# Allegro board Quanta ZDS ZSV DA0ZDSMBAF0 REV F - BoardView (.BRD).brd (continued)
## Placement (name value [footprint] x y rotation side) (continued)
PC169  2200p/50v_4  [C0402]  90.6 23.38 0 bottom
PC170  *0.1u/10v_2  [C0201]  194.69 23.28 0 bottom
PC171  10u/25v_6  [C0603]  160.96 23.08 0 bottom
PC172  1000p/50v_2  [C0201]  188.77 22.88 180 bottom
PC173  0.1u/10v_2  [C0201]  194.69 22.39 180 bottom
PC174  2200p/50v_4  [C0402]  171.67 22.29 0 bottom
PC175  470p/50v_4x  [C0402]  184.51 22.25 0 bottom
PC176  1000p/50v_2  [C0201]  189.33 22.04 180 bottom
PC177  2200p/50v_4  [C0402]  160.4 21.94 180 bottom
PC178  1u/25v_4  [C0402]  179.57 8.11 90 bottom
PC179  *0.1u/10v_2  [C0201]  194.69 21.5 0 bottom
PC180  0.047u/25v_4x  [C0402]  71.76 21.49 0 bottom
PC181  0.1u/10v_2  [C0201]  189.33 21.28 180 bottom
PC182  330p/25v_2  [C0201]  170.63 21.24 90 bottom
PC183  33p/50v_2  [C0201]  172.18 21.22 270 bottom
PC184  10u/25v_6  [C0603]  94.18 20.87 180 bottom
PC185  0.1u/25v_4  [C0402]  160.4 20.95 180 bottom
PC186  0.1u/10v_2  [C0201]  194.69 20.61 0 bottom
PC187  *100p/50v_2  [C0201]  61.19 20.58 0 bottom
PC188  470p/50v_4x  [C0402]  171.42 20.23 180 bottom
PC189  1u/25v_6x  [C0603]  71.17 20.17 180 bottom
PC190  2200p/50v_4  [C0402]  59.9 20.12 270 bottom
PC191  100p/50v_2  [C0201]  62.85 19.79 180 bottom
PC192  0.1u/50v_6x  [C0603]  94.15 19.47 180 bottom
PC193  10u/10v_4  [C0402]  192.76 19.12 90 bottom
PC194  4700p/25v_4x  [C0402]  180.06 19.02 0 bottom
PC195  1000p/50v_2  [C0201]  175.34 18.99 90 bottom
PC196  1000p/50v_2  [C0201]  176.16 18.99 90 bottom
PC197  0.01u/10v_2  [C0201]  177.01 19.16 90 bottom
PC198  1000p/50v_2  [C0201]  178.56 18.99 90 bottom
PC199  330p/25v_2  [C0201]  177.79 19.16 270 bottom
PC200  2200p/50v_4  [C0402]  173.68 18.76 90 bottom
PC201  470p/50v_4x  [C0402]  181.39 18.6 270 bottom
PC202  1000p/50v_2  [C0201]  174.54 18.59 270 bottom
PC203  0.1u/25v_4  [C0402]  86.48 18.4 180 bottom
PC204  100p/50v_2  [C0201]  63.22 18.38 270 bottom
PC205  0.1u/25v_4  [C0402]  68.39 18.29 180 bottom
PC206  0.1u/10v_2  [C0201]  185.27 18.13 0 bottom
PC207  *390p/50v_4  [C0402]  180.06 17.97 0 bottom
PC208  10u/25v_6  [C0603]  73.79 17.83 0 bottom
PC209  *1000p/25v_2  [C0201]  64.13 17.73 0 bottom
PC210  1000p/50v_2  [C0201]  176.73 17.7 0 bottom
PC211  *100p/50v_4  [C0402]  171.04 17.69 90 bottom
PC212  10u/6.3v_6  [C0603]  178.56 2.78 180 bottom
PC213  10u/25v_6  [C0603]  86.47 17.14 180 bottom
PC214  0.1u/25v_4  [C0402]  67.86 16.88 270 bottom
PC215  0.1u/25v_4  [C0402]  68.86 16.88 90 bottom
PC216  10u/25v_6  [C0603]  73.77 16.41 0 bottom
PC217  10u/25v_6  [C0603]  86.47 15.75 180 bottom
PC218  *0.01u/50v_4x  [C0402]  80.42 15.42 180 bottom
PC219  10u/25v_6  [C0603]  73.74 14.94 0 bottom
PC220  *100p/50v_2  [C0201]  69.74 14.34 270 bottom
PC221  10u/25v_6  [C0603]  86.44 14.25 180 bottom
PC222  0.1u/25v_4  [C0402]  73.48 13.66 180 bottom
PC223  1u/25v_4  [C0402]  182.24 6.71 90 bottom
PC224  10u/25v_6  [C0603]  77.4 13.43 90 bottom
PC225  10u/25v_6  [C0603]  75.95 13.42 90 bottom
PC226  2200p/50v_4  [C0402]  74.81 13.21 90 bottom
PC227  0.1u/25v_4  [C0402]  82.29 12.89 270 bottom
PC228  2.2u/10v_4  [C0402]  182.37 14.21 0 bottom
PC229  *100p/50v_2  [C0201]  69.72 12.28 90 bottom
PC230  0.1u/50v_6x  [C0603]  92.32 9.08 0 bottom
PC231  2200p/50v_4  [C0402]  45.44 11.38 0 bottom
PC232  0.1u/25v_4  [C0402]  180.84 7.09 0 bottom
PC233  2.2u/10v_4  [C0402]  192.78 33.38 270 bottom
PC234  0.1u/50v_6x  [C0603]  92.32 10.57 0 bottom
PC235  1u/25v_4  [C0402]  198.75 31.86 270 bottom
PC236  1u/25v_6x  [C0603]  210.69 21.44 270 bottom
PC237  0.1u/25v_4  [C0402]  198.75 29.95 270 bottom
PC238  *10u/10v_4  [C0402]  78.25 46.06 0 bottom
PC239  10u/10v_4  [C0402]  84.63 59.01 270 bottom
PC240  1u/25v_6x  [C0603]  207.89 13.44 90 bottom
PC241  2.2u/10v_4  [C0402]  195.45 11.67 90 bottom
PC242  0.1u/25v_4  [C0402]  201.03 10.27 270 bottom
PC243  1u/25v_4  [C0402]  201.03 12.17 270 bottom
PC244  *2.2u/10v_4  [C0402]  191.76 33.38 270 bottom
PC245  1000p/50v_2  [C0201]  189.48 9.89 0 bottom
PC248  0.1u/10v_2  [C0201]  184.78 10.4 270 bottom
PC249  0.1u/10v_2  [C0201]  184.02 8.62 180 bottom
PC250  0.1u/10v_2  [C0201]  189.48 9 0 bottom
PC251  *0.1u/10v_2  [C0201]  184.14 9.51 90 bottom
PC255  22u/6.3v_6  [C0603]  190.87 6.15 90 bottom
PC256  *22u/6.3v_6  [C0603]  188.72 6.46 0 bottom
PD1  pmeg45a10epd  [D-5_8X4_3-3P]  91.92 16.37 0 bottom
PD2  rb521s30  [D-SOD523-1_2X0_8-1N4148WT-7]  184.02 13.36 90 bottom
PD3  udzvte-175.6b  [DSM]  66.52 14.11 180 bottom
PD4  1n4148wt-7  [D-SOD523-1_2X0_8-1N4148WT-7]  185.41 6.59 0 bottom
PD5  tvs_600w  [D-DO-214AC]  91.99 12.69 180 bottom
PD6  udzvte-175.6b  [DSM]  66.52 12.21 180 bottom
PD7  1n4448ws-7-f  [DSM]  92.54 7.37 0 bottom
PD9  1n4148wt-7  [D-SOD523-1_2X0_8-1N4148WT-7]  201.42 30.97 270 bottom
PD10  rb521s30  [D-SOD523-1_2X0_8-1N4148WT-7]  187.32 12.68 180 bottom
PD11  1n4148wt-7  [D-SOD523-1_2X0_8-1N4148WT-7]  207.64 9.76 270 bottom
PD12  rb521s30  [D-SOD523-1_2X0_8-1N4148WT-7]  188.72 27.16 270 bottom
PD13  1n4148wt-7  [D-SOD523-1_2X0_8-1N4148WT-7]  210.05 3.41 90 bottom
PL1  1.0uh/4.2a_4x4x1.2  [CHOKE-PCMB041B-1R0MS]  74.82 57.19 0 top
PL2  1.5uh/7.2a_7*7*1.5  [L6_6X6_47-1_3]  52.81 53.08 180 top
PL3  0.47uh/5a_4*4*1.2  [L4_2X4_2]  153.13 50.43 180 top
PL4  *0_8/s  [S0805]  160.8 47.87 270 top
PL5  3.3uh_5x5x1.8  [CHOKE-PCMB053T-1R0MS]  82.14 44.72 90 top
PL6  0.15uh/16.7a/7*7*1.5  [CHOKE-MPL73-1R5]  183.56 44.38 0 top
PL7  0.15uh/16.7a/7*7*1.5  [CHOKE-MPL73-1R5]  173.37 44.29 180 top
PL8  1uh/3.35a_2.5x2x1.2  [L3_2X2_5-1_55]  53.25 38.89 180 top
PL9  1.0uh/4.2a_4x4x1.2  [CHOKE-PCMB041B-1R0MS]  58.19 37.9 270 top
PL10  0.47uh/3.7a_2520  [L3_2X2_5-1_55]  68.6 37.3 270 top
PL11  *0_8/s  [S0805]  175.23 33.04 0 bottom
PL12  *0_8/s  [S0805]  181 33.01 180 bottom
PL13  1uh/3.35a_2.5x2x1.2  [L3_2X2_5-1_55]  160.82 29.73 90 bottom
PL14  4.7uh/1.8a_4*4*1.2  [CHOKE-PCMB041B-1R0MS]  79.53 21.76 270 bottom
PL15  *0_8/s  [S0805]  83.87 13.63 90 bottom
PQ1  aon7934  [POWER-3X3-65-10P]  73.96 53.08 270 top
PQ2  aon7934  [POWER-3X3-65-10P]  158.01 49.98 0 top
PQ3  aon7934  [POWER-3X3-65-10P]  61.84 48.61 180 top
PQ4  aon7934  [POWER-3X3-65-10P]  77.26 41.49 0 top
PQ5  aon7934  [POWER-3X3-65-10P]  62.35 38.09 0 top
PQ6  aon6998  [POWER-5X6-1_27-7P]  183.71 37.89 0 top
PQ7  aon6998  [POWER-5X6-1_27-7P]  173.4 37.73 180 top
PQ8  pja3411  [SOT23_213-3_3-2]  50.67 29.06 0 bottom
PQ9  mmdt2907a-7-f  [SOT363-2_1-65-6P]  59.96 25.93 180 bottom
PQ10  aon7934  [POWER-3X3-65-10P]  75.29 21.75 180 bottom
PQ11  aon7410  [WDFN5-3_05X3_05-65]  90.72 20.74 180 bottom
PQ12  aon7410  [WDFN5-3_05X3_05-65]  77.44 16.78 0 bottom
PQ14  aon7401  [WDFN5-3_05X3_05-65]  207.89 26.52 270 bottom
PQ15  me2n7002dkw-g_115ma  [SC70-2_1-65-6P]  212.72 22.08 90 bottom
PQ16  2n7002k_300ma  [SOT23_213-3_3-2]  181.86 3.92 270 bottom
PQ17  aon7401  [WDFN5-3_05X3_05-65]  207.89 21.7 90 bottom
PQ19  2n7002k_300ma  [SOT23_213-3_3-2]  200.78 34.78 0 bottom
PQ20  aon7401  [WDFN5-3_05X3_05-65]  210.69 13.19 270 bottom
PQ21  aon7401  [WDFN5-3_05X3_05-65]  210.69 8.36 90 bottom
PQ22  me2n7002dkw-g_115ma  [SC70-2_1-65-6P]  214.24 8.11 270 bottom
PQ23  mmdt2907a-7-f  [SOT363-2_1-65-6P]  192.53 13.82 0 bottom
PQ24  pja3411  [SOT23_213-3_3-2]  192.14 10.65 180 bottom
PQ26  mmdt2907a-7-f  [SOT363-2_1-65-6P]  194.18 26.91 0 bottom
PQ27  pja3411  [SOT23_213-3_3-2]  189.99 30.97 270 bottom
PQ28  2n7002k_300ma  [SOT23_213-3_3-2]  204.21 10.78 0 bottom
PR1  *0_6/s  [S0603]  86.13 59.2 0 top
PR2  *0_2/s  [S0201]  45.95 58.38 180 top
PR3  *0_8/s  [S0805]  54.73 57.77 0 top
PR4  *0_2/s  [S0201]  45.95 57.54 0 top
PR5  *0_2/s  [S0201]  156.66 56.45 270 top
PR6  *0_6/s  [S0603]  70.25 56.02 0 top
PR7  *0_8/s  [S0805]  79.37 53.33 0 top
PR8  *0_6/s  [S0603]  94.08 52.13 180 top
PR9  *0_6/s  [S0603]  62.61 51.58 180 top
PR10  *0_2  [R0201]  66.54 51.42 270 top
PR11  *10k/f_2  [R0201]  67.33 51.42 270 top
PR12  *0_2/s  [S0201]  68.12 51.42 270 top
PR13  *0_2/s  [S0201]  69.67 51.42 270 top
PR14  *0_2/s  [S0201]  70.5 51.42 270 top
PR15  *0_2/s  [S0201]  65.78 51.42 270 top
PR16  *0_2/s  [S0201]  152.22 50.43 180 top
PR17  *0_2/s  [S0201]  154.12 50.43 0 top
PR18  *0_2/s  [S0201]  75.56 50.43 90 top
PR19  *0_2/s  [S0201]  76.3 50.43 270 top
PR20  ntc_100k_4  [R0402]  170.84 49.09 0 top
PR21  ntc_100k_4  [R0402]  189.24 40.19 0 top
PR22  10k/f_2  [R0201]  51.43 45.91 0 top
PR23  *0_6/s  [S0603]  94.74 48.09 0 top
PR24  150_4  [R0402]  155.57 45.17 270 top
PR25  *0_4/s  [S0402]  189.73 12.05 270 bottom
PR26  *10k/f_2  [R0201]  51.43 45.14 180 top
PR27  *0_6/s  [S0603]  57.02 45.24 180 top
PR28  ntc_100k_4  [R0402]  151.61 47.11 180 top
PR29  *0_4/s  [S0402]  78.79 46.8 270 top
PR30  10k/f_2  [R0201]  51.43 43.87 180 top
PR31  24k/f_4  [R0402]  162.81 43.92 90 top
PR32  10k/f_2  [R0201]  58.41 43.42 270 top
PR33  *0_2/s  [S0201]  57.65 43.42 90 top
PR34  *0_2/s  [S0201]  181.66 44.39 180 top
PR35  *0_2/s  [S0201]  185.44 44.39 0 top
PR36  *0_2/s  [S0201]  175.23 44.34 0 top
PR37  *0_2/s  [S0201]  171.52 44.29 180 top
PR38  *0_2/s  [S0201]  58.41 41.89 90 top
PR39  10k/f_2  [R0201]  51.43 42.27 0 top
PR40  *10k/f_2  [R0201]  51.43 41.51 0 top
PR41  *r010_4  [R0402]  76.3 43.8 0 top
PR42  16.5k/f_2  [R0201]  63.21 46.29 0 top
PR43  *0_2/s  [S0201]  60.73 43.7 0 top
PR44  *0_2/s  [S0201]  60.7 41.99 0 top
PR45  *0_2/s  [S0201]  60.7 42.86 0 top
PR46  *0_6  [R0603]  91.74 42.46 180 top
PR47  *0_2/s  [S0201]  51.43 40.75 0 top
PR48  *0_6/s  [S0603]  86.35 42.28 90 top
PR49  10.2k/f_2  [R0201]  73.4 39.13 90 top
PR50  *0_6/s  [S0603]  71.52 38.22 270 top
PR51  *0_6/s  [S0603]  51.25 35.97 90 top
PR52  *0_6/s  [S0603]  75.35 37.71 90 top
PR53  ntc_100k_4  [R0402]  188.46 36.06 90 top
PR54  *0_2/s  [S0201]  66.17 35.1 90 top
PR55  *0_6/s  [S0603]  71.93 34.52 180 top
PR56  ntc_100k_4  [R0402]  168.47 34.24 90 top
PR57  *0_2/s  [S0201]  164.26 33.84 0 top
PR58  *0_6/s  [S0603]  81.91 59.35 180 bottom
PR59  2.2_6  [R0603]  75.36 55.23 270 bottom
PR60  *0_2/s  [S0201]  78.68 54.65 90 bottom
PR61  *0_2/s  [S0201]  79.83 54.63 90 bottom
PR62  *0_2/s  [S0201]  86.3 53.81 90 top
PR63  *0_2/s  [S0201]  83.84 53.86 90 bottom
PR64  *0_2  [R0201]  84.6 53.86 90 bottom
PR65  *0_2/s  [S0201]  86.3 52.71 270 top
PR66  2.2_6  [R0603]  73.98 52.59 90 bottom
PR67  *0_2  [R0201]  72.42 52.06 0 bottom
PR68  *100k/f_2  [R0201]  71.43 52.06 180 bottom
PR69  2.2_6  [R0603]  158.72 50.93 180 bottom
PR70  *0_2/s  [S0201]  88.92 50.76 180 bottom
PR71  *0_2/s  [S0201]  72.11 50.71 270 bottom
PR72  10.2k/f_2  [R0201]  71.24 50.69 90 bottom
PR73  *0_2/s  [S0201]  85.72 50.66 0 bottom
PR74  *0_2  [R0201]  88.92 50.05 180 bottom
PR75  *0_2/s  [S0201]  85.72 49.88 0 bottom
PR76  *0_2/s  [S0201]  74.85 49.62 270 bottom
PR77  *0_2/s  [S0201]  71.96 49.6 270 bottom
PR78  100/f_2  [R0201]  116.63 49.56 90 bottom
PR79  100/f_2  [R0201]  117.49 49.56 90 bottom
PR80  100/f_2  [R0201]  118.33 49.56 90 bottom
PR81  100/f_2  [R0201]  119.14 49.56 90 bottom
PR82  1_6  [R0603]  158.72 49.43 0 bottom
PR83  *0_4/s  [S0402]  75.59 49.32 90 bottom
PR84  *10k/f_2  [R0201]  64.93 49.12 180 bottom
PR85  *0_2  [R0201]  65.73 48.99 90 bottom
PR86  *0_2/s  [S0201]  66.59 48.99 90 bottom
PR87  *0_2/s  [S0201]  67.89 49.04 90 bottom
PR88  100k/f_2  [R0201]  68.78 48.99 90 bottom
PR89  *0_2/s  [S0201]  69.95 48.99 270 bottom
PR90  *0_2/s  [S0201]  61.34 48.96 270 bottom
PR91  *0_2/s  [S0201]  70.7 48.77 90 bottom
PR92  10k/f_2  [R0201]  71.57 48.71 0 bottom
PR93  *0_2/s  [S0201]  72.97 48.35 90 bottom
PR94  *0_2/s  [S0201]  73.68 48.35 90 bottom
PR95  *0_2/s  [S0201]  74.49 48.17 0 bottom
PR96  *0_2/s  [S0201]  64.69 48.17 180 bottom
PR97  *0_2/s  [S0201]  69.63 47.86 0 bottom
PR98  *0_2/s  [S0201]  90.42 47.86 180 bottom
PR99  *100k/f_2  [R0201]  71.57 47.31 0 bottom
PR100  *2.2_6  [R0603]  59.69 47.74 180 bottom
PR101  *100k/f_2  [R0201]  65.73 47.72 270 bottom
PR102  *0_2/s  [S0201]  66.49 47.72 270 bottom
PR103  *0_2/s  [S0201]  68.32 47.56 180 bottom
PR104  *10k/f_2  [R0201]  74.49 47.36 180 bottom
PR105  249k/f_2  [R0201]  69.63 47.09 180 bottom
PR106  2.2_6  [R0603]  63.57 46.68 90 bottom
PR107  *62k/f_2  [R0201]  68.4 46.45 0 bottom
PR108  1m/f_2  [R0201]  69.62 46.39 0 bottom
PR109  *0_2/s  [S0201]  66.87 46.37 270 bottom
PR110  *0_2/s  [S0201]  65.73 46.32 90 bottom
PR111  *0_2  [R0201]  91.46 45.98 180 bottom
PR112  *0_2  [R0201]  85.41 45.12 270 bottom
PR113  *0_2/s  [S0201]  86.13 45.12 270 bottom
PR114  *0_2/s  [S0201]  90.49 45.74 90 bottom
PR115  1k/f_2  [R0201]  69.69 45.43 90 bottom
PR116  *0_2/s  [S0201]  68.4 45.41 180 bottom
PR117  *10k/f_2  [R0201]  66.87 45.13 90 bottom
PR118  100/f_2  [R0201]  126.49 45.04 180 bottom
PR119  *10k/f_2  [R0201]  74.49 45 180 bottom
PR120  100k/f_2  [R0201]  71.72 44.77 0 bottom
PR121  *10k/f_2  [R0201]  51.43 43.87 0 bottom
PR122  100/f_2  [R0201]  125.6 44.48 90 bottom
PR123  *0_2/s  [S0201]  68.4 44.39 180 bottom
PR124  *0_2  [R0201]  69.79 44.39 180 bottom
PR125  *0_2  [R0201]  75.91 44.36 90 bottom
PR126  *0_2/s  [S0201]  70.68 44.26 270 bottom
PR127  *0_2/s  [S0201]  74.59 44.16 180 bottom
PR128  *10k/f_2  [R0201]  66.87 43.91 270 bottom
PR129  *0_2  [R0201]  51.43 43.03 0 bottom
PR130  10.2k/f_2  [R0201]  68.4 43.4 180 bottom
PR131  100k/f_2  [R0201]  69.82 43.4 0 bottom
PR132  *0_2/s  [S0201]  70.86 43.3 90 bottom
PR133  *57.6k/f_2  [R0201]  73.73 43.14 180 bottom
PR134  *0_2/s  [S0201]  69.31 42.65 180 bottom
PR135  *0_2/s  [S0201]  51.43 42.27 180 bottom
PR136  *0_2/s  [S0201]  72.51 42.53 270 bottom
PR137  2.2_6  [R0603]  61.87 42.23 180 bottom
PR138  *0_2/s  [S0201]  73.73 42.13 180 bottom
PR139  2.2_6  [R0603]  80.61 42.1 90 bottom
PR140  100k/f_2  [R0201]  69.79 41.93 0 bottom
PR141  *2.2_6  [R0603]  52.6 40.19 90 bottom
PR142  *0_2  [R0201]  65.22 41.49 270 bottom
PR143  *0_2/s  [S0201]  66.13 41.49 270 bottom
PR144  2.2_6  [R0603]  76.42 41.47 0 bottom
PR145  *0_4/s  [S0402]  56.6 40.34 90 bottom
PR146  *0_2/s  [S0201]  67.89 41.21 180 bottom
PR147  *0_2/s  [S0201]  65.09 40.33 90 bottom
PR148  *10k/f_2  [R0201]  70.91 40.27 90 bottom
PR149  *0_2/s  [S0201]  72.61 40.27 90 bottom
PR150  100k/f_2  [R0201]  73.96 40.27 270 bottom
PR151  *0_2/s  [S0201]  66.49 40.22 90 bottom
PR152  *0_2  [R0201]  68.12 40.22 270 bottom
PR153  *0_2  [R0201]  68.85 40.22 270 bottom
PR154  *2.2_6  [R0603]  59.03 40.15 270 bottom
PR155  *0_2/s  [S0201]  67.3 39.87 270 bottom
PR156  100k/f_2  [R0201]  70.02 39.18 270 bottom
PR157  100k/f_2  [R0201]  66.52 39.16 270 bottom
PR158  100k/f_2  [R0201]  68.27 39.16 270 bottom
PR159  100k/f_2  [R0201]  69.21 39.16 270 bottom
PR160  100k/f_2  [R0201]  70.91 39.16 270 bottom
PR161  *0_2/s  [S0201]  71.77 39.16 270 bottom
PR162  *0_2  [R0201]  72.61 39.16 90 bottom
PR163  2.2_6  [R0603]  172.94 38.75 270 bottom
PR164  2.2_6  [R0603]  183.36 38.6 270 bottom
PR165  100/f_2  [R0201]  53.74 36.97 180 bottom
PR166  *0_2/s  [S0201]  52.42 36.97 180 bottom
PR167  100/f_2  [R0201]  53.72 35.97 0 bottom
PR168  *0_2/s  [S0201]  113.84 35.36 270 bottom
PR169  *0_2/s  [S0201]  114.89 35.35 270 bottom
PR170  *0_2/s  [S0201]  80.61 34.86 90 bottom
PR171  *0_6/s  [S0603]  62.15 34.38 90 bottom
PR172  *0_2/s  [S0201]  54.25 33.83 0 bottom
PR173  *0_2/s  [S0201]  69.97 33.75 180 bottom
PR174  *0_2/s  [S0201]  54.25 33.15 0 bottom
PR175  100/f_2  [R0201]  69.97 32.93 180 bottom
PR176  *0_6/s  [S0603]  159.35 32.77 0 bottom
PR177  *0_8/s  [S0805]  59.33 32.59 0 bottom
PR178  *0_6/s  [S0603]  76.12 31.59 270 bottom
PR179  *0_6/s  [S0603]  81.86 30.77 90 bottom
PR180  *2.2_6  [R0603]  163.63 30.28 0 bottom
PR181  1_6  [R0603]  175.23 30.27 270 bottom
PR182  2.2_6  [R0603]  172.31 30.24 270 bottom
PR183  1_6  [R0603]  181.1 30.22 270 bottom
PR184  243k/f_4  [R0402]  170.05 29.86 90 bottom
PR185  14k/f_4  [R0402]  176.4 29.86 90 bottom
PR186  4.32k/f_4  [R0402]  171.04 29.86 90 bottom
PR187  11k/f_4  [R0402]  178.94 29.86 90 bottom
PR188  11k/f_4  [R0402]  179.88 29.81 90 bottom
PR189  15.8k/f_4  [R0402]  184.37 29.73 180 bottom
PR190  *0_2/s  [S0201]  183.99 28.86 180 bottom
PR191  *0_2/s  [S0201]  184.86 28.62 270 bottom
PR192  *0_2/s  [S0201]  185.64 28.62 270 bottom
PR193  931/f_4  [R0402]  187.37 29.04 90 bottom
PR194  1k/f_2  [R0201]  169.74 27.96 180 bottom
PR195  *0_2  [R0201]  158.47 27.9 0 bottom
PR196  *0_4/s  [S0402]  163.99 27.86 180 bottom
PR197  2k/f_2  [R0201]  187.27 27.52 270 bottom
PR198  *0_2/s  [S0201]  71.83 27.46 180 bottom
PR199  *0_2  [R0201]  73.26 27.46 180 bottom
PR200  1k/f_2  [R0201]  184.57 27.24 90 bottom
PR201  15.8k/f_4  [R0402]  169.41 27 0 bottom
PR202  510k_2  [R0201]  57.52 26.87 180 bottom
PR203  *0_2/s  [S0201]  171.02 26.8 0 bottom
PR204  100k/f_2  [R0201]  68.56 26.74 0 bottom
PR205  10k/f_2  [R0201]  157.63 26.68 270 bottom
PR206  *10k/f_2  [R0201]  158.64 26.68 270 bottom
PR207  1k/f_2  [R0201]  185.85 26.64 0 bottom
PR208  *0_4  [R0402]  34.08 26.47 90 bottom
PR209  *0_2  [R0201]  71.85 26.37 180 bottom
PR210  *0_2/s  [S0201]  73.25 26.37 180 bottom
PR211  *0_4/s  [S0402]  55.92 26.23 180 bottom
PR212  10/f_4  [R0402]  65.48 26.59 270 bottom
PR213  10/f_4  [R0402]  170.66 26.02 0 bottom
PR214  1k/f_2  [R0201]  57.42 26.01 180 bottom
PR215  18.7k/f_4  [R0402]  68.85 25.82 180 bottom
PR216  *100k/f_2  [R0201]  64.52 25.74 90 bottom
PR217  220k_2  [R0201]  61.86 25.63 90 bottom
PR218  *2.2_6  [R0603]  79.37 25.54 180 bottom
PR219  *0_6/s  [S0603]  190.7 25.79 90 bottom
PR220  *1k/f_2  [R0201]  57.42 25.14 180 bottom
PR221  11k/f_4  [R0402]  184.43 25.14 180 bottom
PR222  *0_2/s  [S0201]  164.55 25.12 270 bottom
PR223  *0_4  [R0402]  55.92 24.92 180 bottom
PR224  *0_2/s  [S0201]  168.47 24.79 270 bottom
PR225  *0_2  [R0201]  63.83 24.74 180 bottom
PR226  1m/f_2  [R0201]  61.86 24.46 270 bottom
PR227  *10k/f_2  [R0201]  158.51 23.6 180 bottom
PR228  7.5k/f_2  [R0201]  186.56 24.32 90 bottom
PR229  220k_2  [R0201]  60.01 24.28 180 bottom
PR230  *0_2/s  [S0201]  196.18 24.17 180 bottom
PR231  *0_2/s  [S0201]  163.04 24.05 0 bottom
PR232  165k/f_4  [R0402]  169.71 24.04 180 bottom
PR233  10k/f_2  [R0201]  164.46 24.02 0 bottom
PR234  *0_2/s  [S0201]  62.79 23.96 0 bottom
PR235  *0_4/s  [S0402]  175.38 10.27 270 bottom
PR236  10k/f_2  [R0201]  158.51 22.92 0 bottom
PR237  14k/f_4  [R0402]  186.48 23.35 180 bottom
PR238  *0_2  [R0201]  196.18 23.28 180 bottom
PR239  *0_2/s  [S0201]  62.77 23.19 0 bottom
PR240  75k/f_2  [R0201]  170.28 23.1 90 bottom
PR241  15.8k/f_4  [R0402]  168.97 23.08 180 bottom
PR242  *0_4/s  [S0402]  71.76 22.53 0 bottom
PR243  10k/f_2  [R0201]  158.51 22.19 0 bottom
PR244  *0_2/s  [S0201]  62.75 22.43 0 bottom
PR245  *0_2  [R0201]  196.18 22.39 0 bottom
PR246  *0_6/s  [S0603]  163.69 22.32 180 bottom
PR247  21k/f_4  [R0402]  186.47 22.25 180 bottom
PR248  49.9/f_2  [R0201]  170.22 22.19 180 bottom
PR249  15.4k/f_4  [R0402]  60.75 21.61 0 bottom
PR250  *0_2/s  [S0201]  196.18 21.5 0 bottom
PR251  *10k/f_2  [R0201]  158.54 21.43 180 bottom
PR252  1k/f_2  [R0201]  169.82 21.24 90 bottom
PR253  3.3k/f_2  [R0201]  171.42 21.21 270 bottom
PR254  10/f_4  [R0402]  184.55 21.2 0 bottom
PR255  88.7k/f_4  [R0402]  168.96 20.87 270 bottom
PR256  *0_4/s  [S0402]  62.47 20.76 180 bottom
PR257  220/f_2  [R0201]  185.27 20.46 0 bottom
PR258  *0_2/s  [S0201]  182.22 20.38 90 bottom
PR259  *0_2/s  [S0201]  183.82 20.29 180 bottom
PR260  rc1206-r010  [F3_2X1_65-2_8]  85.81 20.26 180 bottom
PR261  *0_2/s  [S0201]  86.52 20.26 0 bottom
PR262  *0_2/s  [S0201]  85.07 20.23 180 bottom
PR263  *0_2  [R0201]  159.33 19.91 90 bottom
PR264  *0_2/s  [S0201]  158.3 19.91 90 bottom
PR265  75/f_2  [R0201]  187.24 19.82 90 bottom
PR266  300/f_4  [R0402]  61.47 19.76 180 bottom
PR267  *56.2/f_2  [R0201]  185.27 19.68 180 bottom
PR268  *75/f_2  [R0201]  186.33 19.6 0 bottom
PR269  49.9/f_2  [R0201]  183.82 19.55 0 bottom
PR270  39k/f_4  [R0402]  171.42 19.19 0 bottom
PR271  *0_6/s  [S0603]  190.9 19.17 90 bottom
PR272  100/f_2  [R0201]  185.27 18.91 180 bottom
PR273  24.3k/f_4  [R0402]  182.84 18.61 270 bottom
PR274  10k/f_2  [R0201]  64.14 18.44 0 bottom
PR275  1k/f_2  [R0201]  172.71 19.16 270 bottom
PR276  100k/f_2  [R0201]  65.43 18.33 270 bottom
PR277  4.02k/f_2  [R0201]  66.37 18.31 270 bottom
PR278  4.02k/f_2  [R0201]  67.13 18.31 270 bottom
PR279  300/f_4  [R0402]  62.31 18.09 270 bottom
PR280  10/f_8  [R0805]  70.84 17.86 270 bottom
PR281  1k/f_2  [R0201]  177.7 17.67 0 bottom
PR282  *44.2k/f_4  [R0402]  172.05 17.69 270 bottom
PR283  10k/f_4  [R0402]  178.71 17.51 270 bottom
PR284  536/f_4  [R0402]  175.66 17.46 90 bottom
PR285  *0_2/s  [S0201]  174.82 17.39 90 bottom
PR286  *0_2/s  [S0201]  173.34 17.37 90 bottom
PR287  *0_2/s  [S0201]  174.06 17.36 90 bottom
PR288  100k/f_2  [R0201]  65.43 17.29 270 bottom
PR289  rc1206-r010  [F3_2X1_65-2_8]  82.53 17.2 0 bottom
PR290  *0_2/s  [S0201]  83.21 17.2 0 bottom
PR291  *0_2/s  [S0201]  81.82 17.17 180 bottom
PR292  62k/f_2  [R0201]  64.14 17.05 0 bottom
PR293  14k/f_4  [R0402]  180.03 17.03 0 bottom
PR294  *0_2/s  [S0201]  182.14 17.01 90 bottom
PR295  7.5k/f_2  [R0201]  181.35 17.01 90 bottom
PR296  1k/f_2  [R0201]  177.67 16.98 180 bottom
PR297  *0_2  [R0201]  183.18 16.96 90 bottom
PR298  *0_2/s  [S0201]  183.97 16.96 90 bottom
PR299  *0_2/s  [S0201]  184.55 16.96 90 bottom
PR300  51.1k/f_4  [R0402]  185.53 16.59 270 bottom
PR301  *0_2/s  [S0201]  176.42 16.2 90 bottom
PR302  *0_2/s  [S0201]  177.16 16.2 90 bottom
PR303  10k/f_2  [R0201]  182.27 16.09 180 bottom
PR304  *0_2/s  [S0201]  67.84 15.5 0 bottom
PR305  12.4k/f_4  [R0402]  176.78 3.03 90 bottom
PR306  10k/f_4  [R0402]  175 3.03 90 bottom
PR307  14k/f_4  [R0402]  175.89 3.03 270 bottom
PR308  *0_2/s  [S0201]  80.34 14.53 0 bottom
PR309  330_4  [R0402]  71.09 13.58 0 bottom
PR310  470_6  [R0603]  210.59 25.89 90 bottom
PR311  *0_4/s  [S0402]  183.13 6.71 270 bottom
PR312  1m_4  [R0402]  78.86 12.89 90 bottom
PR313  100_4  [R0402]  80.26 12.89 270 bottom
PR314  330_4  [R0402]  71.09 12.64 0 bottom
PR315  18.7k/f_4  [R0402]  182.37 13.19 180 bottom
PR316  1m/f_2  [R0201]  184.4 5.32 0 bottom
PR317  10k/f_2  [R0201]  180.76 13.19 180 bottom
PR318  100k/f_2  [R0201]  209.92 24.11 180 bottom
PR319  10k/f_2  [R0201]  183.25 5.32 180 bottom
PR320  10k/f_2  [R0201]  180.97 6.33 0 bottom
PR321  100k/f_2  [R0201]  208.91 24.11 180 bottom
PR324  100k/f_2  [R0201]  213.48 19.41 180 bottom
PR325  27.4k/f_4  [R0402]  192.78 31.48 270 bottom
PR326  100k/f_2  [R0201]  214.5 19.41 270 bottom
PR327  *0_4/s  [S0402]  199.64 31.86 90 bottom
PR328  10k/f_2  [R0201]  214.75 18.14 180 bottom
PR330  *0_2/s  [S0201]  213.48 18.14 180 bottom
PR331  10k/f_2  [R0201]  200.27 30.08 270 bottom
PR332  10.2k/f_2  [R0201]  192.78 29.95 270 bottom
PR334  10k/f_2  [R0201]  199.64 30.08 90 bottom
PR335  *100k/f_2  [R0201]  212.59 18.14 270 bottom
PR337  1m/f_2  [R0201]  201.67 37.19 90 bottom
PR340  *0_2  [R0201]  65.09 47.23 90 bottom
PR341  *0_2  [R0201]  158.54 20.73 0 bottom
PR342  *0_2  [R0201]  158.51 24.43 0 bottom
PR491  *10k/f_2  [R0201]  62.81 3.21 90 bottom
PR492  *0_2/s  [S0201]  176.27 12.3 270 bottom
PR493  *0_2/s  [S0201]  175.51 12.22 270 bottom
PR494  *0_2  [R0201]  177.03 12.3 270 bottom
PR495  10k/f_2  [R0201]  180.08 14.45 270 bottom
PR496  *100k/f_2  [R0201]  213.35 14.97 180 bottom
PR497  470_6  [R0603]  212.34 5.19 180 bottom
PR498  *100k/f_2  [R0201]  217.42 13.44 180 bottom
PR499  10k/f_2  [R0201]  213.99 11.67 0 bottom
PR500  *100k/f_2  [R0201]  217.42 14.21 180 bottom
PR501  100k/f_2  [R0201]  214.12 10.78 0 bottom
PR502  *0_2/s  [S0201]  215.26 11.67 0 bottom
PR503  100k/f_2  [R0201]  212.97 10.78 180 bottom
PR504  100k/f_2  [R0201]  211.96 10.78 180 bottom
PR505  100k/f_2  [R0201]  215.26 10.78 0 bottom
PR506  220k_2  [R0201]  194.68 13.82 180 bottom
PR507  27.4k/f_4  [R0402]  194.56 11.67 270 bottom
PR508  10k/f_2  [R0201]  201.92 9.51 270 bottom
PR509  1k/f_2  [R0201]  194.68 14.59 0 bottom
PR510  1m/f_2  [R0201]  206.5 12.05 90 bottom
PR512  1m/f_2  [R0201]  190.49 14.84 180 bottom
PR513  1m/f_2  [R0201]  194.68 13.06 0 bottom
PR514  220k_2  [R0201]  190.49 14.08 0 bottom
PR515  *0_4/s  [S0402]  201.92 12.17 270 bottom
PR516  10.2k/f_2  [R0201]  194.56 10.27 270 bottom
PR517  10k/f_2  [R0201]  201.92 10.65 270 bottom
PR518  1m/f_2  [R0201]  194.68 28.56 0 bottom
PR519  220k_2  [R0201]  196.56 26.65 90 bottom
PR520  220k_2  [R0201]  192.53 28.43 270 bottom
PR521  1k/f_2  [R0201]  196.34 27.79 0 bottom
PR522  *0_4/s  [S0402]  190.11 28.05 90 bottom
PR523  1m/f_2  [R0201]  193.54 28.56 0 bottom
PR524  *0_6/s  [S0603]  188.72 7.73 180 bottom
PR525  *0_2/s  [S0201]  184.78 9.51 270 bottom
PR526  *0_6/s  [S0603]  40.25 55.23 270 top
PU1  aoz1331di  [SON14-3X2-4-15P-SMT]  82.67 56.64 0 top
PU2  ncp81253  [DFN8-2X2-5-9P-NCP5901]  157.06 54.27 180 top
PU3  aoz1331di  [SON14-3X2-4-15P-SMT]  91.61 49.42 270 top
PU4  tmp708aidbvr  [SOT23-5-2_8-95-5P-G708]  159.89 44.13 0 top
PU5  tps650832  [BGA168-TEXAS-TPS650830ZAJT]  69.52 45.23 180 top
PU6  aoz1331di  [SON14-3X2-4-15P-SMT]  88.82 44.67 180 top
PU7  nb681agd-z  [QFN13-2X3-5]  54.51 42.57 180 top
PU8  mc74vhc1g08dft2g  [SOT353-1-2_125-65-5P]  88.56 52.93 180 top
PU9  aoz1331di  [SON14-3X2-4-15P-SMT]  79.17 32.1 0 bottom
PU10  mc74vhc1g08dft2g  [SOT353-1-2_125-65-5P]  76 27.47 180 bottom
PU11  nb681agd-z  [QFN13-2X3-5]  161.36 25.83 180 bottom
PU12  ncp81206  [QFN52-6X6-4-53P-1H]  178.12 24.46 90 bottom
PU13  aoz1331di  [SON14-3X2-4-15P-SMT]  191.99 22.55 270 bottom
PU14  bq24780sruyr  [QFN28-4X4-4-38P]  66.43 22.08 180 bottom
PU15  g9661mre1u  [TDFN10-3X3-5-11P-APL5620QBI-TRG]  177.21 6.92 180 bottom
PU16  ap2204k-adjtrg1  [SOT23-5-2_8-95-5P-1_3H]  181.93 10.14 270 bottom
PU17  ap2204k-adjtrg1  [SOT23-5-2_8-95-5P-1_3H]  195.7 30.84 0 bottom
PU18  *mc74vhc1g08dft2g  [SOT353-1-2_125-65-5P]  213.99 16.62 180 bottom
PU19  mc74vhc1g08dft2g  [SOT353-1-2_125-65-5P]  177.03 14.33 180 bottom
PU20  *mc74vhc1g08dft2g  [SOT353-1-2_125-65-5P]  214.88 13.44 0 bottom
PU21  ap2204k-adjtrg1  [SOT23-5-2_8-95-5P-1_3H]  198.24 11.54 0 bottom
PU22  aoz1331di  [SON14-3X2-4-15P-SMT]  186.94 10.14 90 bottom
Q1  dmg301nu-7_220ma  [SOT23_213-3_3-2]  103.47 58.49 180 top
Q2  metr3904-g_200ma  [SOT23_213-3_3-2]  98.52 58.46 0 top
Q3  metr3904-g_200ma  [SOT23_213-3_3-2]  108.17 58.46 180 top
Q4  *2n7002k_300ma  [SOT23_213-3_3-2]  192.02 39.99 0 top
Q8  *pja138k_500ma  [SOT23_213-3_3-2]  186.81 32.75 180 bottom
Q10  *14@me2n7002dkw-g_115ma  [SC70-2_1-65-6P]  190.37 48.55 90 bottom
Q11  *14@me2n7002dkw-g_115ma  [SC70-2_1-65-6P]  194.33 48.5 90 bottom
Q12  2n7002k_300ma  [SOT23_213-3_3-2]  198.29 39.99 0 bottom
Q13  *2n7002k_300ma  [SOT23_213-3_3-2]  193.42 39.66 0 bottom
Q14  *2n7002k_300ma  [SOT23_213-3_3-2]  93.54 27.64 90 bottom
Q15  2n7002k_300ma  [SOT23_213-3_3-2]  90.85 25.94 180 bottom
Q16  *pj4n3kdw  [SC70-2_1-65-6P]  43.53 30.27 270 bottom
Q17  pja138k_500ma  [SOT23_213-3_3-2]  40.46 27.9 270 bottom
Q18  *2n7002kdw_115ma  [SC70-2_1-65-6P]  228.21 27.54 0 bottom
Q19  rq3e100bnfu7tb_10a  [PG-TSDSON-8-8P-R]  199.51 26.78 270 bottom
Q20  2n7002k_300ma  [SOT23_213-3_3-2]  204.21 18.4 0 bottom
Q21  2n7002k_300ma  [SOT23_213-3_3-2]  42.82 22.3 90 bottom
Q22  metr3904-g_200ma  [SOT23_213-3_3-2]  46.65 22.3 90 bottom
Q23  ltc044eubfs8tl_30ma  [UMT_213-3-1_3]  41.5 17.47 90 bottom
Q24  metr3904-g_200ma  [SOT23_213-3_3-2]  188.44 17.51 0 bottom
Q25  2n7002k_300ma  [SOT23_213-3_3-2]  213.35 26.78 270 bottom
Q26  2n7002kdw_115ma  [SC70-2_1-65-6P]  216.4 25.13 90 bottom
Q27  14@2n7002k_300ma  [SOT23_213-3_3-2]  161.36 14.76 180 bottom
Q28  *ao3404  [SOT23_213-3_3-2]  226.43 12.43 270 bottom
Q29  2n7002k_300ma  [SOT23_213-3_3-2]  235.83 18.65 270 bottom
Q30  *ddtc144eua-7-f_30ma  [UMT_213-3-1_3]  219.32 11.03 270 bottom
Q31  2n7002k_300ma  [SOT23_213-3_3-2]  65.32 8.97 270 bottom
Q33  14@2n7002kdw_115ma  [SC70-2_1-65-6P]  146.32 3.69 270 bottom
Q34  *pja138k_500ma  [SOT23_213-3_3-2]  230.24 12.43 270 bottom
Q48  *dmn601dwk-7  [SC70-2_1-65-6P]  161.13 10.93 180 bottom
Q6062  *poa@ao3413  [SOT23_213-3_3-2]  172.97 11.54 0 bottom
Q6063  *ao3413  [SOT23_213-3_3-2]  167.1 10.92 270 bottom
Q6064  2n7002kdw_115ma  [SC70-2_1-65-6P]  61.56 30.08 0 bottom
Q6066  2n7002kdw_115ma  [SC70-2_1-65-6P]  129.66 9.53 180 bottom
Q6067  *me2n7002dkw-g_115ma  [SC70-2_1-65-6P]  53.21 25.25 270 bottom
Q6068  *2n7002k_300ma  [SOT23_213-3_3-2]  204.21 14.59 0 bottom
Q6069  *2n7002k_300ma  [SOT23_213-3_3-2]  185.67 3.92 270 bottom
Q6070  rq3e100bnfu7tb_10a  [PG-TSDSON-8-8P-R]  203.57 6.97 180 bottom
Q6071  2n7002k_300ma  [SOT23_213-3_3-2]  189.48 3.92 270 bottom
Q6072  2n7002kdw_115ma  [SC70-2_1-65-6P]  57.35 22.37 180 bottom
R1  *0_2/s  [S0201]  46.91 42.81 90 top
R2  1k/f_2  [R0201]  101.01 59.47 0 top
R3  *0_4/s  [S0402]  41.8 44.69 180 bottom
R4  *0_4  [R0402]  43.66 44.69 0 bottom
R4L1  243/f_4  [R0402]  110.79 9.51 270 bottom
R4L2  243/f_4  [R0402]  111.86 9.51 270 bottom
R5  *0_2/s  [S0201]  47.54 42.81 90 top
R5L1  243/f_4  [R0402]  133.32 13.99 0 bottom
R5L2  243/f_4  [R0402]  132.89 13.02 0 bottom
R6  *1k/f_2  [R0201]  42.51 42.76 270 top
R6L1  243/f_4  [R0402]  155.98 40.3 0 bottom
R6L2  243/f_4  [R0402]  155.8 28.95 0 bottom
R6L3  243/f_4  [R0402]  155.8 27.93 0 bottom
R7  *10_2  [R0201]  101.04 57.28 180 top
R7A1  243/f_4  [R0402]  155.98 41.32 0 bottom
R8  15/f_2  [R0201]  49.04 42.81 270 top
R9  1k/f_2  [R0201]  43.3 42.76 90 top
R10  *0_2/s  [S0201]  48.25 42.81 90 top
R11  15/f_2  [R0201]  44.14 42.76 90 top
R12  1k/f_2  [R0201]  101.04 56.45 180 top
R13  1k/f_2  [R0201]  45.31 42.76 90 top
R14  15/f_2  [R0201]  45.16 49.64 90 top
R15  15/f_2  [R0201]  46.15 42.76 270 top
R16  *0_2/s  [S0201]  44.39 49.64 270 top
R17  *0_2/s  [S0201]  42.89 49.67 270 top
R18  15/f_2  [R0201]  43.63 49.66 90 top
R19  *0_2  [R0201]  124.05 54.07 270 top
R20  51.1/f_2  [R0201]  124.73 54.07 90 top
R21  *0_2  [R0201]  125.55 54.07 270 top
R22  1k/f_2  [R0201]  129.3 53.4 90 top
R23  *0_2  [R0201]  130.17 53.4 90 top
R24  *0_2  [R0201]  130.96 53.38 90 top
R25  *51.1/f_2  [R0201]  131.69 53.38 270 top
R26  *0_2  [R0201]  121.41 52.82 90 top
R27  *2.2k_2  [R0201]  103.78 52.74 270 top
R28  *2.2k_2  [R0201]  104.59 52.74 270 top
R29  10k/f_2  [R0201]  106.14 52.74 90 top
R30  100/f_2  [R0201]  112.04 52.73 90 top
R31  *0_2/s  [S0201]  106.98 52.72 90 top
R32  *10k/f_2  [R0201]  108.65 52.71 90 top
R33  10k/f_2  [R0201]  109.49 52.71 90 top
R34  10k/f_2  [R0201]  110.33 52.71 90 top
R35  100/f_2  [R0201]  111.15 52.54 180 top
R36  *10k/f_2  [R0201]  101.77 51.42 180 top
R37  *10_2  [R0201]  102.97 51.24 0 top
R38  10k/f_2  [R0201]  104.82 50.99 180 top
R39  *100k/f_4  [R0402]  44.19 53.7 270 top
R40  10k/f_2  [R0201]  97.05 50.84 270 top
R41  *0_2  [R0201]  101.77 50.79 180 top
R42  *0_2/s  [S0201]  101.77 50.12 0 top
R43  *0_2/s  [S0201]  104.87 50.12 180 top
R45  *10k/f_2  [R0201]  103.37 49.72 180 top
R46  10k/f_2  [R0201]  104.87 49.26 180 top
R47  *0_2/s  [S0201]  43.05 56.75 0 top
R48  *0_2  [R0201]  43.05 55.99 0 top
R49  1m_4  [R0402]  104.97 47.35 270 top
R50  2.7k/f_2  [R0201]  105 46.01 180 top
R51  10k/f_2  [R0201]  103.78 45.33 0 top
R52  1k/f_2  [R0201]  105 45.33 0 top
R53  113/f_4  [R0402]  102.48 45.27 0 top
R54  1k/f_2  [R0201]  100.63 44.69 90 top
R55  *10k/f_2  [R0201]  105 44.62 0 top
R56  *10k/f_2  [R0201]  105 43.91 0 top
R57  ram@xxx  [R0201]  104.08 43.6 270 top
R58  ram@xxx  [R0201]  101.87 43.6 0 top
R59  ram@xxx  [R0201]  102.99 43.6 0 top
R60  *2.2k_2  [R0201]  97.61 43.4 180 top
R61  *4.7k_2  [R0201]  96.51 43.37 180 top
R62  10k/f_2  [R0201]  105 43.2 180 top
R63  *0_4  [R0402]  41.52 49.99 0 top
R64  *10k/f_2  [R0201]  101.87 42.89 0 top
R65  10k/f_2  [R0201]  102.86 42.71 270 top
R66  *2.2k_2  [R0201]  97.61 42.69 180 top
R67  *4.7k_2  [R0201]  96.51 42.66 180 top
R68  ram@xxx  [R0201]  105 42.51 180 top
R69  ram@xxx  [R0201]  101.87 42.18 0 top
R70  ram@xxx  [R0201]  103.04 41.69 0 top
R71  ccg2@10k/f_2  [R0201]  99.99 42.04 180 top
R73  *0_2  [R0201]  41.7 41.7 0 top
R74  200/f_2  [R0201]  104.92 41.67 180 top
R75  *10k/f_2  [R0201]  100.76 39.84 180 top
R76  ccg4@10k/f_2  [R0201]  99.99 41.28 0 top
R77  *10k/f_2  [R0201]  98.7 41.26 180 top
R78  *4.7k_2  [R0201]  104.92 41.04 180 top
R80  13@10k/f_2  [R0201]  101.87 40.82 0 top
R81  *100k/f_4  [R0402]  41.7 40.81 180 top
R82  14@10k/f_2  [R0201]  102.97 40.96 0 top
R83  *1k_2  [R0201]  104.03 40.78 270 top
R84  200/f_2  [R0201]  104.92 40.29 180 top
R86  *10k/f_2  [R0201]  101.87 40.06 0 top
R87  *10k/f_2  [R0201]  101.87 41.49 0 top
R88  *0_4  [R0402]  41.7 39.79 0 top
R89  20k/f_4  [R0402]  96.77 39.77 270 top
R90  *1k_2  [R0201]  104.92 39.58 0 top
R91  *10k/f_2  [R0201]  199.08 39.44 0 top
R92  *10k/f_2  [R0201]  101.77 39.41 0 top
R93  10k/f_2  [R0201]  102.92 39.41 0 top
R94  10k/f_2  [R0201]  100.75 39.1 180 top
R95  20k/f_4  [R0402]  94.74 39.77 90 top
R96  *0_2/s  [S0201]  199.05 38.65 180 top
R97  *1k_2  [R0201]  100.75 38.28 0 top
R98  *1k/f_2  [R0201]  101.87 38.39 180 top
R99  10k/f_2  [R0201]  103.17 38.28 180 top
R100  *14@0_2  [R0201]  83.71 38.16 90 top
R101  *14@0_2/s  [S0201]  84.42 38.16 90 top
R102  *10k/f_2  [R0201]  103.27 37.53 180 top
R103  *10k/f_2  [R0201]  102.13 37.68 180 top
R104  *0_4/s  [S0402]  99.42 39.5 180 top
R105  *0_2  [R0201]  105.17 37.45 270 top
R106  *debug@0_2/s  [S0201]  199.08 37.23 180 top
R107  22/f_2  [R0201]  104.36 36.87 270 top
R108  *0_2  [R0201]  101.93 36.33 180 top
R109  *0_2  [R0201]  103.17 36.79 180 top
R110  8.2k/f_2  [R0201]  100.78 36.66 180 top
R111  *debug@0_2/s  [S0201]  199.08 36.46 180 top
R112  debug@22/f_2  [R0201]  105.18 36.46 270 top
R113  *10k/f_2  [R0201]  103.09 35.75 180 top
R114  10k/f_2  [R0201]  101.92 35.67 180 top
R115  *0_4  [R0402]  99.64 35.73 90 top
R116  *debug@0_2/s  [S0201]  199.08 35.7 180 top
R117  10k/f_2  [R0201]  219.2 13.82 270 bottom
R118  *0_2/s  [S0201]  101.92 35.04 0 top
R119  10k/f_2  [R0201]  103.09 35.03 0 top
R120  *debug@0_2/s  [S0201]  199.08 34.94 180 top
R121  10k/f_2  [R0201]  218.31 25.89 90 bottom
R122  162/f_2  [R0201]  130.42 36.94 180 top
R123  *14@0_2/s  [S0201]  80.84 34.38 270 top
R124  *4.7k_2  [R0201]  95.22 34.23 180 top
R125  49.9/f_2  [R0201]  103.78 34.08 180 top
R126  49.9/f_2  [R0201]  104.59 33.41 270 top
R127  200/f_2  [R0201]  130.42 36.18 180 top
R128  *4.7k_2  [R0201]  95.22 33.59 180 top
R129  80.6/f_2  [R0201]  130.42 35.36 180 top
R130  *4.7k_2  [R0201]  95.22 32.98 180 top
R131  10m_4  [R0402]  103.75 32.93 90 top
R133  *4.7k_2  [R0201]  95.22 32.27 180 top
R135  1k/f_2  [R0201]  103.8 31.58 180 top
R136  *0_2  [R0201]  94.1 32.2 180 top
R139  *0_4  [R0402]  260.29 12.61 270 top
R140  *0_4  [R0402]  261.31 12.61 270 top
R141  100k/f_4  [R0402]  34.97 58.84 270 bottom
R142  *0_2/s  [S0201]  189.22 33.64 90 bottom
R143  *100k/f_2  [R0201]  105.05 58.21 0 bottom
R144  *1m/f_2  [R0201]  106.85 57.74 180 bottom
R145  *0_4/s  [S0402]  46.27 42.53 0 bottom
R146  *0_4/s  [S0402]  112.29 56.37 270 bottom
R149  *0_4  [R0402]  46.27 44.69 0 bottom
R150  14@931/f_4  [R0402]  182.73 55.14 270 bottom
R151  13@169/f_4  [R0402]  186.53 55.13 270 bottom
R152  13@130/f_4  [R0402]  189.38 55.13 270 bottom
R153  13@169/f_4  [R0402]  190.32 55.13 270 bottom
R154  13@130/f_4  [R0402]  192.22 55.13 270 bottom
R155  14@604/f_4  [R0402]  184.61 55.13 270 bottom
R156  1k/f_2  [R0201]  126.16 53.22 0 bottom
R157  14@931/f_4  [R0402]  180.64 53.13 270 bottom
R158  14@604/f_4  [R0402]  181.66 53.13 270 bottom
R160  *0_4/s  [S0402]  115.18 51.24 0 bottom
R161  1k/f_2  [R0201]  121.1 52.71 270 bottom
R162  *14@0_2/s  [S0201]  192.96 52.79 180 bottom
R163  49.9/f_2  [R0201]  123.26 52.43 180 bottom
R164  60.4/f_2  [R0201]  126.57 52.12 270 bottom
R165  *14@0_2/s  [S0201]  192.96 53.45 180 bottom
R166  220/f_2  [R0201]  125.04 51.32 90 bottom
R167  56.2/f_2  [R0201]  125.8 51.32 270 bottom
R168  499/f_2  [R0201]  121.1 51.07 270 bottom
R169  *14@4.7k_2  [R0201]  192.73 50.33 270 bottom
R170  220/f_4  [R0402]  125.02 49.91 90 bottom
R171  *14@0_6/s  [S0603]  200.5 46.95 270 bottom
R172  60.4/f_2  [R0201]  121.33 49.3 270 bottom
R173  *0_2  [R0201]  122.17 49.12 270 bottom
R174  *14@4.7k_2  [R0201]  192.73 49.24 90 bottom
R175  24.9/f_2  [R0201]  123.14 49 270 bottom
R176  49.9/f_2  [R0201]  124.15 49.07 90 bottom
R177  *14@4.7k_2  [R0201]  188.77 48.91 90 bottom
R178  *14@0_2  [R0201]  195.93 48.66 90 bottom
R179  *14@0_2  [R0201]  191.87 48.58 90 bottom
R180  *14@0_2  [R0201]  192.73 48.05 270 bottom
R183  1k/f_2  [R0201]  125.63 47.86 90 bottom
R184  *14@0_2  [R0201]  188.77 47.84 270 bottom
R186  *14@4.7k_2  [R0201]  195.93 47.51 270 bottom
R187  150/f_2  [R0201]  114.32 47 180 bottom
R188  4.7k_2  [R0201]  108.27 43.85 180 bottom
R189  *10k/f_2  [R0201]  110.77 43.74 90 bottom
R190  4.7k_2  [R0201]  108.27 43.11 180 bottom
R191  4.7k_2  [R0201]  109.11 43.72 90 bottom
R192  4.7k_2  [R0201]  109.82 43.47 90 bottom
R193  24.9/f_2  [R0201]  138.63 40.73 180 bottom
R194  *0_2  [R0201]  196.01 40.02 90 bottom
R195  10/f_2  [R0201]  138.63 39.97 0 bottom
R196  1m_4  [R0402]  113.79 38.97 180 bottom
R197  *0_4  [R0402]  138.48 38.88 0 bottom
R198  10k/f_4  [R0402]  196.01 38.52 90 bottom
R199  *0_2  [R0201]  192.09 37.73 180 bottom
R200  8.2k/f_2  [R0201]  138.6 37.84 180 bottom
R201  *0_2/s  [S0201]  192.09 38.5 180 bottom
R202  10k/f_2  [R0201]  199.08 37.23 0 bottom
R203  10k/f_2  [R0201]  106.88 36.99 270 bottom
R204  10k/f_2  [R0201]  107.77 36.99 270 bottom
R205  10k/f_2  [R0201]  106.09 36.99 270 bottom
R206  10k/f_2  [R0201]  108.92 36.56 0 bottom
R207  *0_2/s  [S0201]  105.45 35.87 0 bottom
R208  10k/f_2  [R0201]  106.75 35.87 180 bottom
R209  *debug@0_2/s  [S0201]  198.37 35.8 0 bottom
R211  *0_4  [R0402]  110.21 34.96 270 bottom
R212  *debug@0_2/s  [S0201]  198.37 35.03 0 bottom
R213  *0_2/s  [S0201]  106.75 34.85 0 bottom
R214  10k/f_2  [R0201]  108.02 34.85 0 bottom
R216  *0_2  [R0201]  105.54 34.04 270 bottom
R217  *0_2  [R0201]  106.75 33.83 0 bottom
R218  *0_2  [R0201]  108.02 33.83 0 bottom
R219  *0_4  [R0402]  111.27 33.26 90 bottom
R220  *0_4/s  [S0402]  110.21 33.24 90 bottom
R222  *10_2  [R0201]  109.09 33.03 180 bottom
R223  100k/f_2  [R0201]  106.75 32.82 180 bottom
R224  *0_2/s  [S0201]  105.53 32.62 270 bottom
R226  *0_8/s  [S0805]  191.38 34.78 90 top
R227  *0_2/s  [S0201]  108.02 32.21 180 bottom
R228  *0_2  [R0201]  106.75 32.11 0 bottom
R229  *100k/f_4  [R0402]  90.85 28.91 0 bottom
R230  *0_2  [R0201]  87.6 30.55 0 bottom
R231  *0_8/s  [S0805]  193.29 34.78 90 top
R232  *0_2  [R0201]  98.5 29.96 180 bottom
R236  *10_2  [R0201]  97.05 28.79 90 bottom
R238  33/f_2  [R0201]  102.69 28.29 0 bottom
R240  *0_4/s  [S0402]  34.08 28.18 270 bottom
R241  *2.2k_2  [R0201]  249.55 28.3 180 bottom
R242  33/f_2  [R0201]  101.39 27.5 0 bottom
R243  *100k/f_2  [R0201]  198.11 15.35 0 bottom
R244  1k/f_2  [R0201]  97.53 27.47 0 bottom
R245  33/f_2  [R0201]  102.69 27.47 0 bottom
R247  24.9/f_2  [R0201]  124 27.45 0 bottom
R249  *10k/f_4  [R0402]  43.68 27.32 270 bottom
R250  *0_4  [R0402]  45.15 27.32 90 bottom
R251  *0_4  [R0402]  46.17 27.32 90 bottom
R252  100k/f_2  [R0201]  250.79 27.22 0 bottom
R253  *100k/f_2  [R0201]  251.89 27.22 180 bottom
R254  *0_4  [R0402]  121.05 27.11 270 bottom
R255  *0_2/s  [S0201]  248.97 27.22 90 bottom
R256  *0_2/s  [S0201]  249.73 27.22 90 bottom
R257  8.2k/f_2  [R0201]  122.35 27.07 270 bottom
R258  8.2k/f_2  [R0201]  107.26 26.99 90 bottom
R259  *0_2/s  [S0201]  224.66 27.54 270 bottom
R260  *0_2/s  [S0201]  225.6 28.33 270 bottom
R262  33/f_2  [R0201]  97.53 26.77 0 bottom
R263  10/f_2  [R0201]  124 26.69 180 bottom
R264  100k/f_4  [R0402]  204.34 20.81 180 bottom
R265  10k/f_2  [R0201]  200.02 13.57 0 bottom
R266  2.2k_2  [R0201]  230.88 28.3 180 bottom
R269  4.7k_2  [R0201]  254.05 26.08 90 bottom
R273  2.2k_2  [R0201]  230.88 27.41 180 bottom
R274  *1m_4  [R0402]  199.64 18.27 180 bottom
R275  10k/f_4  [R0402]  43.74 24.9 180 bottom
R276  *10k/f_4  [R0402]  41.81 24.9 0 bottom
R279  5.1/f_2  [R0201]  155.42 24.75 270 bottom
R280  24.9/f_2  [R0201]  156.28 24.75 90 bottom
R281  2.2k_2  [R0201]  45.59 24.66 0 bottom
R282  100k/f_4  [R0402]  46.98 24.66 0 bottom
R283  *0_4/s  [S0402]  200.91 23.98 0 bottom
R284  *0_6  [R0603]  254.25 30.08 270 bottom
R285  *0_6/s  [S0603]  241.6 18.12 90 bottom
R290  *0_2  [R0201]  82.57 24.19 90 bottom
R291  *0_2  [R0201]  83.38 24.19 90 bottom
R292  *100k/f_4  [R0402]  201.54 18.27 180 bottom
R295  *0_2/s  [S0201]  247.75 24.26 90 bottom
R296  *0_6/s  [S0603]  203.57 25.64 180 bottom
R297  *0_6/s  [S0603]  203.57 27.16 180 bottom
R298  *0_6  [R0603]  232.02 17.76 0 bottom
R299  52.3k/f_4  [R0402]  202.94 21.95 180 bottom
R300  93.1k/f_4  [R0402]  202.94 22.97 180 bottom
R301  8.2k/f_2  [R0201]  155.75 22.8 180 bottom
R302  *4.7k_2  [R0201]  255.26 22.59 180 bottom
R303  *4.7k_2  [R0201]  256.41 22.59 0 bottom
R304  *4.7k_2  [R0201]  246.37 22.33 270 bottom
R305  *4.7k_2  [R0201]  247.14 22.33 270 bottom
R306  8.2k/f_2  [R0201]  155.75 22.04 0 bottom
R307  *0_4/s  [S0402]  234.18 22.08 180 bottom
R308  *10k/f_4  [R0402]  234.18 21.06 0 bottom
R309  10k/f_4  [R0402]  232.28 21.06 0 bottom
R310  *0_6/s  [S0603]  239.9 18.14 270 bottom
R311  *0_6  [R0603]  237.05 28.15 180 bottom
R313  *0_4  [R0402]  155.77 21.1 180 bottom
R314  *4.7k_2  [R0201]  56.18 19.95 180 bottom
R318  *4.7k_2  [R0201]  246.37 20.68 270 bottom
R319  *4.7k_2  [R0201]  247.14 20.68 270 bottom
R320  47k/f_2  [R0201]  50.01 20.97 270 bottom
R321  *10k/f_2  [R0201]  51.23 20.97 270 bottom
R323  *0_4  [R0402]  56.2 18.61 270 bottom
R324  8.2k/f_2  [R0201]  138.37 20.51 0 bottom
R325  *0_4  [R0402]  43.66 43.59 0 bottom
R326  *1k_2  [R0201]  104.92 38.87 0 top
R327  *0_2/s  [S0201]  7.74 20.31 0 bottom
R329  10k/f_4  [R0402]  41.21 20.28 0 bottom
R330  *4.7k_2  [R0201]  54.45 19.95 0 bottom
R331  4.7k_2  [R0201]  59 19.93 270 bottom
R332  4.7k_2  [R0201]  59.73 22.8 270 bottom
R333  *4.7k_2  [R0201]  255.39 19.67 180 bottom
R334  *4.7k_2  [R0201]  256.41 19.67 0 bottom
R335  *0_2/s  [S0201]  7.74 19.55 0 bottom
R336  mll@33/f_2  [R0201]  50.01 19.55 270 bottom
R337  4.7k_2  [R0201]  54.93 21.95 90 bottom
R338  mll@33/f_2  [R0201]  45.13 18.99 270 bottom
R339  mll@33/f_2  [R0201]  45.77 18.99 270 bottom
R341  *0_4  [R0402]  54.4 18.63 270 bottom
R342  15/f_2  [R0201]  51.25 18.58 90 bottom
R344  15/f_2  [R0201]  52.12 18.35 90 bottom
R345  10k/f_2  [R0201]  53 18.35 270 bottom
R346  22k_4  [R0402]  254.88 16.24 270 bottom
R347  *4.7k_2  [R0201]  253.49 18.02 90 bottom
R350  *0_6/s  [S0603]  36.21 17.38 90 bottom
R351  10k/f_4  [R0402]  253.87 16.24 90 bottom
R352  *0_2  [R0201]  47.42 17.19 90 bottom
R353  10k/f_2  [R0201]  51.56 24.65 90 bottom
R354  *0_2/s  [S0201]  49.04 17.19 90 bottom
R355  *0_6/s  [S0603]  6.65 17.43 0 bottom
R356  15/f_2  [R0201]  52.12 17.08 90 bottom
R357  15/f_2  [R0201]  52.98 17.08 90 bottom
R358  10k/f_2  [R0201]  51.56 25.79 270 bottom
R359  100k/f_2  [R0201]  53.79 17.06 90 bottom
R360  4.7k_2  [R0201]  54.55 17.06 90 bottom
R361  2.2k_2  [R0201]  58.31 17.05 180 bottom
R362  ccg2@10k/f_2  [R0201]  55.39 17.03 270 bottom
R363  4.99k/f_4  [R0402]  256.03 16.87 270 bottom
R364  *10k/f_4  [R0402]  234.18 20.05 0 bottom
R365  *10k/f_4  [R0402]  232.28 20.05 0 bottom
R366  *4.7k_2  [R0201]  254.25 18.02 90 bottom
R367  10/f_2  [R0201]  60.29 16.8 0 bottom
R368  ccg4@10k/f_2  [R0201]  54.22 20.94 90 bottom
R370  mll@2.2_6  [R0603]  44.11 16.17 270 bottom
R371  *0_4  [R0402]  235.58 21.44 90 bottom
R372  10k/f_4  [R0402]  236.59 21.44 90 bottom
R373  100k/f_2  [R0201]  60.29 16.02 180 bottom
R374  *0_4  [R0402]  248.1 15.96 0 bottom
R377  33/f_2  [R0201]  246.68 15.71 180 bottom
R378  10k/f_4  [R0402]  61.92 15.59 0 bottom
R379  *0_4/s  [S0402]  249.85 15.51 180 bottom
R380  *1m_6  [R0603]  217.04 11.03 270 bottom
R381  *0_6/s  [S0603]  242.69 14.87 270 bottom
R382  *14@0_2/s  [S0201]  165.25 16.85 180 bottom
R383  *14@0_2/s  [S0201]  165.25 15.83 180 bottom
R384  100k/f_2  [R0201]  63.75 14.72 0 bottom
R386  2.2k_2  [R0201]  59.89 14.69 180 bottom
R387  43_4  [R0402]  58.39 14.65 180 bottom
R389  *100k/f_4  [R0402]  41.45 14.31 90 bottom
R390  14@4.7k_2  [R0201]  160.24 16.97 180 bottom
R391  *14@0_2  [R0201]  161.27 16.95 0 bottom
R392  *0_4/s  [S0402]  43.78 14.24 0 bottom
R393  *0_6/s  [S0603]  251.33 14.21 90 bottom
R395  100k/f_4  [R0402]  252.57 14.14 90 bottom
R396  *0_4  [R0402]  253.54 14.14 270 bottom
R397  *0_4  [R0402]  254.55 14.14 90 bottom
R399  2.2k_2  [R0201]  216.78 22.59 0 bottom
R402  *0_4/s  [S0402]  246.17 13.88 90 bottom
R404  *14@0_2/s  [S0201]  164.01 16.85 180 bottom
R405  *14@0_2/s  [S0201]  164.01 15.83 180 bottom
R408  *0_2/s  [S0201]  16.87 12.44 90 bottom
R409  *10k/f_2  [R0201]  45.13 12.49 0 bottom
R410  *0_6/s  [S0603]  18.46 12.15 180 bottom
R411  14@4.7k_2  [R0201]  162.82 16.85 180 bottom
R412  14@4.7k_2  [R0201]  162.82 15.83 180 bottom
R413  14@100k/f_2  [R0201]  156.92 12.43 0 bottom
R414  2.2k_2  [R0201]  216.78 21.7 0 bottom
R416  2.2k_2  [R0201]  216.78 20.81 0 bottom
R417  *0_6/s  [S0603]  223.89 11.79 270 bottom
R418  200k/f_4  [R0402]  253.16 10.71 0 bottom
R420  *14@100k/f_2  [R0201]  165.75 14.99 0 bottom
R421  *14@100k/f_2  [R0201]  165.73 14.16 0 bottom
R422  2.2k_2  [R0201]  256.33 10.45 0 bottom
R423  *0_4/s  [S0402]  258.36 10.45 180 bottom
R425  *0_4  [R0402]  221.48 11.41 90 bottom
R426  100k/f_2  [R0201]  17.11 10.11 270 bottom
R427  1k/f_2  [R0201]  16.28 10.1 270 bottom
R429  mll@33/f_2  [R0201]  45 9.91 90 bottom
R430  *14@100k/f_2  [R0201]  164.66 14.69 270 bottom
R432  1k/f_2  [R0201]  237.1 13.7 180 bottom
R433  *100k/f_4  [R0402]  222.62 11.79 270 bottom
R434  100k/f_4  [R0402]  62.45 9.13 180 bottom
R435  14@100k/f_2  [R0201]  166.87 14.99 0 bottom
R436  *14@0_2/s  [S0201]  167.89 14.16 180 bottom
R439  *10k/f_4  [R0402]  237.1 14.59 180 bottom
R441  *0_2/s  [S0201]  133.98 8.23 0 bottom
R442  100k/f_2  [R0201]  16.16 8.42 90 bottom
R443  mll@33/f_2  [R0201]  16.91 8.42 270 bottom
R444  10k/f_4  [R0402]  132.9 8.62 270 bottom
R445  *14@100k/f_2  [R0201]  166.87 14.16 0 bottom
R446  14@100k/f_2  [R0201]  166.87 13.32 0 bottom
R447  2.2k_2  [R0201]  256.33 8.17 0 bottom
R448  *0_4/s  [S0402]  258.36 8.17 180 bottom
R450  10k/f_4  [R0402]  132.92 6.71 90 bottom
R451  *0_2/s  [S0201]  133.98 7.09 0 bottom
R452  14@100k/f_2  [R0201]  165.73 13.32 180 bottom
R455  *14@0_2  [R0201]  145.89 6.03 180 bottom
R456  14@4.7k_2  [R0201]  145.89 6.76 0 bottom
R457  14@100k/f_2  [R0201]  165.73 12.48 180 bottom
R459  *14@0_2  [R0201]  146.27 9.48 180 bottom
R460  *14@0_2/s  [S0201]  147.16 9.53 90 bottom
R461  14@4.7k_2  [R0201]  146.96 10.5 180 bottom
R462  mll@33/f_2  [R0201]  45.78 5.82 180 bottom
R466  *14@0_2  [R0201]  146.27 8.67 0 bottom
R467  *14@0_2/s  [S0201]  147.16 8.31 270 bottom
R472  *10k/f_4  [R0402]  257.09 5.25 270 bottom
R473  14@4.7k_2  [R0201]  146.27 7.96 0 bottom
R474  *0_4/s  [S0402]  239.08 5.04 270 bottom
R475  *0_4  [R0402]  240.41 5.04 270 bottom
R477  62_4  [R0402]  258.49 4.87 0 bottom
R478  *4.7k_2  [R0201]  50.79 4.86 270 bottom
R479  4.7k_4  [R0402]  255.57 4.74 0 bottom
R481  0_4  [R0402]  144.77 10.22 180 bottom
R482  *10_2  [R0201]  55.26 4.68 270 bottom
R483  2.2k_2  [R0201]  56.61 4.68 90 bottom
R484  *0_6/s  [S0603]  142.56 3.26 180 bottom
R485  mll@2.2_6  [R0603]  51.81 4.07 270 bottom
R486  100k/f_4  [R0402]  250.49 3.72 0 bottom
R487  *14@0_2/s  [S0201]  163.8 14.59 270 bottom
R488  14@4.7k_2  [R0201]  146.88 6.76 180 bottom
R489  *14@0_2  [R0201]  146.88 6.03 180 bottom
R490  *10k/f_4  [R0402]  56.2 3.06 270 bottom
R492  *29.4k/f_4  [R0402]  239.06 3.14 90 bottom
R493  *10k/f_4  [R0402]  257.09 3.09 270 bottom
R494  *0_4  [R0402]  243.89 2.91 270 bottom
R495  *10k/f_4  [R0402]  240.38 2.96 0 bottom
R496  4.7k_4  [R0402]  255.57 2.71 0 bottom
R497  62_4  [R0402]  258.49 2.71 0 bottom
R499  14@100k/f_2  [R0201]  168.35 12.1 180 bottom
R500  *14@100k/f_2  [R0201]  168.35 12.81 0 bottom
R501  *0_2  [R0201]  106.75 31.3 0 bottom
R502  *0_2/s  [S0201]  105.12 37.47 180 bottom
R503  *0_2  [R0201]  104.03 37.47 0 bottom
R504  *0_4  [R0402]  46.27 43.59 0 bottom
R505  *0_2/s  [S0201]  84.75 24.11 270 bottom
R514  1k/f_2  [R0201]  127.12 8.74 0 bottom
R543  1k/f_2  [R0201]  127.12 9.63 0 bottom
R659  **poa@0_2  [R0201]  174.11 7.86 270 bottom
R668  **0_2  [R0201]  160.55 9.35 180 bottom
R675  *1k_4  [R0402]  158.57 10.73 270 bottom
R676  *1k_4  [R0402]  163.7 11.13 90 bottom
R677  **0_2  [R0201]  161.66 9.35 0 bottom
R860  **poa@0_2  [R0201]  170.61 12.76 180 bottom
R1526  *poa@0_2  [R0201]  173.22 3.64 270 bottom
R1527  *poa@0_2  [R0201]  172.51 3.64 270 bottom
R1528  *poa@0_2  [R0201]  173.22 2.52 270 bottom
R1529  *poa@0_2  [R0201]  172.51 2.52 270 bottom
R1530  **poa@0_2  [R0201]  170.48 11.77 90 bottom
R1531  **poa@0_2  [R0201]  173.22 4.76 270 bottom
R1532  **poa@0_2  [R0201]  172.51 4.76 270 bottom
R1533  **poa@0_2  [R0201]  173.2 8.11 270 bottom
R1534  **poa@0_2  [R0201]  172.49 8.11 270 bottom
R10930  **poa@10_2  [R0201]  174.87 6.97 0 bottom
R10931  **poa@0_2  [R0201]  170.61 13.6 180 bottom
R10932  *poa@0_2  [R0201]  170.61 14.43 180 bottom
R10934  *poa@10k/f_2  [R0201]  174.52 13.85 270 bottom
R10941  *0_4  [R0402]  169.49 11.89 90 bottom
R10942  *1k_2  [R0201]  108.27 42.4 180 bottom
R10943  *1k_2  [R0201]  108.27 41.69 180 bottom
R10944  *0_2  [R0201]  48.25 17.63 90 bottom
R10946  *0_2/s  [S0201]  50.54 24.77 180 bottom
R10947  *0_2/s  [S0201]  50.54 25.66 180 bottom
R10948  *0_2  [R0201]  49.9 4.81 270 bottom
R10949  *0_2  [R0201]  49.14 4.81 270 bottom
R10950  100k/f_2  [R0201]  252.47 28.18 270 bottom
R10951  10k/f_2  [R0201]  63.93 26.68 0 bottom
R10952  1k/f_2  [R0201]  62.78 26.68 180 bottom
R10953  13@0_2  [R0201]  243.96 17.63 0 bottom
R10954  13@0_2  [R0201]  244.98 17.63 180 bottom
R10955  14@0_2  [R0201]  244.98 16.87 180 bottom
R10956  14@0_2  [R0201]  243.96 16.87 0 bottom
R10957  *10k/f_4  [R0402]  164.08 9.63 180 bottom
R10959  *0_2  [R0201]  45.94 13.42 270 bottom
R10960  *0_2/s  [S0201]  45.94 14.43 90 bottom
R10961  *0_2  [R0201]  45.84 6.71 180 bottom
